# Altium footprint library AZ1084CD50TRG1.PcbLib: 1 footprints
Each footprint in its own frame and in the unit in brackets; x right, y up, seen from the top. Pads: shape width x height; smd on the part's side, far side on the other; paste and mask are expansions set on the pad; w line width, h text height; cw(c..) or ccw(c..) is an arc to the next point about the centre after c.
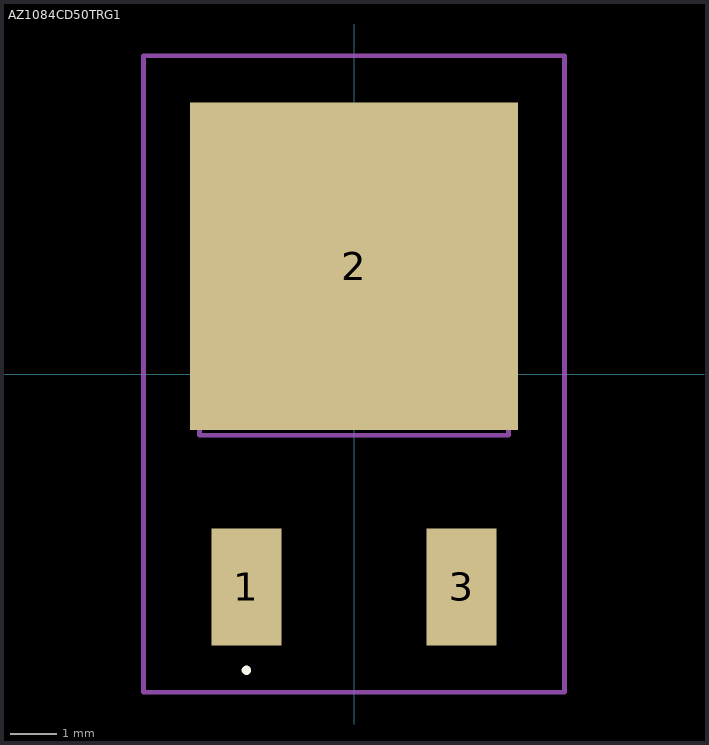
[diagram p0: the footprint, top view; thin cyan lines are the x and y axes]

## AZ1084CD50TRG1 [mm]
pads (3):
  rect 1.5x2.5 smd: 1(-2.3,-4.55) 3(2.3,-4.55)
  rect 7x7 smd: 2(0,2.3)
Top Overlay:
  lines w0.1: -2.3,-6.381 cw(c-2.3,-6.331) -2.3,-6.281 ; -2.3,-6.381 -2.3,-6.381 ; -2.3,-6.381 ccw(c-2.3,-6.331) -2.3,-6.281 ; -2.3,-6.281 -2.3,-6.281
Mechanical 15:
  lines w0.1: -3.3,-1.312 3.3,-1.312 3.3,4.788 -3.3,4.788 -3.3,-1.312
Mechanical 20:
  lines w0.1: -4.5,-6.8 4.5,-6.8 4.5,6.8 -4.5,6.8 -4.5,-6.8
